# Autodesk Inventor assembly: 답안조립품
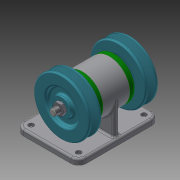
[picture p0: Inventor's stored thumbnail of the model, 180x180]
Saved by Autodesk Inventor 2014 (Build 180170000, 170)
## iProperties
Created: 2019-09
Part Number: 답안조립품
Document SubType Name: Assembly
Designer: kh
Author: kh
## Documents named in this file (10)
- C:\Users\kh\Desktop\490904V1017\답안조립품.iam
- C:\Users\kh\Desktop\490904V1017\본체.ipt
- C:\Users\kh\Desktop\490904V1017\V-벨트풀리.ipt
- C:\Users\kh\Desktop\490904V1017\너트 M10x1.ipt
- C:\Users\kh\Desktop\490904V1017\베어링 6004.ipt
- C:\Users\kh\Desktop\490904V1017\볼트 M4.ipt
- C:\Users\kh\Desktop\490904V1017\오일 실 17 30 5.ipt
- C:\Users\kh\Desktop\490904V1017\축.ipt
- C:\Users\kh\Desktop\490904V1017\커버.ipt
- C:\Users\kh\Desktop\490904V1017\키 5 x 5 x 12.ipt
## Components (2 placed, 1 different names)
1. V-벨트풀리:1 — Insert:1, Mate:2, Insert:16
2. V-벨트풀리:2 — Insert:2, Mate:1, Insert:17
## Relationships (6: Insert 4, Mate 2)
- Insert:1: V-벨트풀리:1
- Insert:2: V-벨트풀리:2
- Mate:1: V-벨트풀리:2
- Mate:2: V-벨트풀리:1
- Insert:16: V-벨트풀리:1
- Insert:17: V-벨트풀리:2
